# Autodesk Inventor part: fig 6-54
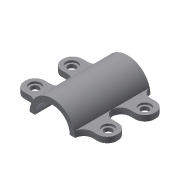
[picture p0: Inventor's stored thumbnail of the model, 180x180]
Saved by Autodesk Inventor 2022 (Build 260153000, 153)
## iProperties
Created: 2004-05
Part Number: fig 6-54
Document SubType Name: Modeling
Designer: CADCIM Technologies
Manufacturer: Standard
Standards Organization: Custom
Density: 1 g/cm^3
Material: Generic
Appearance: Default
Author: CADCIM Technologies
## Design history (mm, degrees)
node "Sketch1"
sketch "Sketch2"
  geometry: L1 (23.378, 0)-(17.996, 0); L2 (-17.996, 0)-(-23.378, 0); A1 r 23.378 centre (0, 0) between (23.378, 0) and (-23.378, 0); A2 r 17.996 centre (0, 0) between (17.996, 0) and (-17.996, 0)
  constraints: 4 end point, 4 point on circle, 2 centre point, 1 collinear, 1 horizontal
extrude "Extrusion1" new body sketch "Sketch2" stored distance "d0" = 38.75; taper "d1" = 0 deg
sketch "Sketch3"
  geometry: L1 (23.378, 0)-(17.996, 0); L2 (-17.996, 0)-(-23.378, 0) reference; L3 (-23.378, 0)-(-47.662, 0); L4 (-47.662, 0)-(-47.662, 5.722); L5 (-47.662, 5.722)-(-22.667, 5.722); A1 r 17.996 centre (0, 0) between (17.996, 0) and (-17.996, 0) reference; A2 r 23.378 centre (0, 0) between (23.378, 0) and (-23.378, 0) reference; 1 further point
  constraints: 10 end point, 5 point on circle, 2 centre point, 1 collinear, 1 horizontal, 1 midpoint, 1 parallel, 1 perpendicular, 3 other
extrude "Extrusion2" join sketch "Sketch3" stored distance "d2" = 21; taper "d3" = 0 deg
fillet "Fillet1" dims "d4" = 10
hole "Hole1" diameter "d7" = 8; stored, may be unused: countersink angle "d11" = 90 deg, drill point angle "d13" = 118 deg; dims "d5" = 10, "d6" = 10, "d8" = 6, "d9" = 12, "d10" = 2, "d12" = 12
fillet "Fillet2" dims "d14" = 9.5
mirror "Mirror1"
mirror "Mirror2"
body "Solid1"
